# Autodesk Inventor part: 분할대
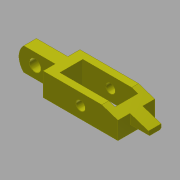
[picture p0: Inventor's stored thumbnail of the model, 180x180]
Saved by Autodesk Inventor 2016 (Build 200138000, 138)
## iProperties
Created: 2016-11
Part Number: 분할대
Material: 강철, 연강
Document SubType Name: Modeling
Designer: mduedu
Density: 1 g/cm^3
Appearance: 노란색
Author: mduedu
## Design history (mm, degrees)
sketch "스케치1"
  geometry: L1 (32.5, 16)-(-32.5, 16); L2 (-32.5, 16)-(-32.5, -16); L3 (-32.5, -16)-(32.5, -16); L4 (32.5, -16)-(32.5, 16); L5 (24, 10)-(-24, 10); L6 (-24, 10)-(-24, -10); L7 (-24, -10)-(24, -10); L8 (24, -10)-(24, 10); L9 (24, 0)-(-24, 0); L10 (0, -16)-(0, 16); 4 further points
  constraints: 20 end point, 7 midpoint, 4 parallel, 2 coincident, 2 horizontal, 2 perpendicular, 1 horizontal alignment
  dimensions: "d0" = 20 distance of L5.end L6.end; "d2" = 32 distance between parallel lines of L1 L3; "d3" = 48 distance of L5.start L5.end; "d4" = 65 distance of L1.start L1.end
extrude "돌출1" new body sketch "스케치1" distance "d5" = 20; taper "d6" = 0 deg
sketch "스케치2"
  geometry: L1 (0, 0)-(65, 0) reference; L2 (65, 0)-(65, 20) reference; L3 (0, 20)-(65, 20) reference; L4 (0, 0)-(0, 20) reference; L5 (32.5, 0)-(32.5, 20); C1 r 4 at (32.5, 10)
  constraints: 2 end point, 2 midpoint, 1 centre point
  dimensions: "d7" = 8 diameter of C1
extrude "돌출2" cut sketch "스케치2" stored distance "d8" = 20; taper "d9" = 0 deg
chamfer "모따기1" distance "d10" = 0.2; stored, may be unused: second distance "d11" = 2, angle "d12" = 45 deg
sketch "스케치3"
  geometry: L1 (-32.5, 0)-(-32.5, 20) reference; L2 (-32.5, 20)-(-59.798, 20); L3 (-64, 20)-(-64, 0); L4 (-64, 0)-(-59.798, 0); L5 (-32.5, 0)-(-32.5, 20); L6 (-59.798, 20)-(-64, 20); L7 (-59.798, 0)-(-32.5, 0); C1 r 4.2 at (0, 10) reference; C2 r 5 at (-50, 10); A1 r 14 centre (-50, 10) between (-59.798, 20) and (-59.798, 0); 1 further point
  constraints: 12 end point, 5 parallel, 2 centre point, 2 horizontal, 2 perpendicular, 2 point on circle, 1 coincident, 1 horizontal alignment, 1 tangent
  dimensions: "d13" = 64 distance from line of L3 C1.centre; "d14" = 14 radius of A1; "d15" = 10 diameter of C2
extrude "돌출3" join sketch "스케치3" stored distance "d16" = 11; taper "d17" = 0 deg
sketch "스케치4"
  geometry: L1 (32.5, 0)-(32.5, 20) reference; L2 (32.5, 20)-(48.5, 20); L3 (48.5, 20)-(48.5, 6); L4 (48.5, 6)-(32.5, 6); L5 (32.5, 6)-(32.5, 20); L6 (32.5, 0)-(-32.5, 0) reference; 1 further point
  constraints: 8 end point, 2 parallel, 1 horizontal, 1 perpendicular
  dimensions: "d18" = 16 distance of L1.end L2.end; "d19" = 6 distance between parallel lines of L4 L6
extrude "돌출4" join sketch "스케치4" stored distance "d20" = 11; taper "d21" = 0 deg
chamfer "모따기2" distance "d22" = 30; stored, may be unused: second distance "d23" = 10, angle "d24" = 45 deg
chamfer "모따기3" distance "d25" = 1; stored, may be unused: second distance "d26" = 10, angle "d27" = 45 deg
chamfer "모따기4" distance "d28" = 0.2; stored, may be unused: second distance "d29" = 10, angle "d30" = 45 deg
node "솔리드1"
node "투영된 루프1"
